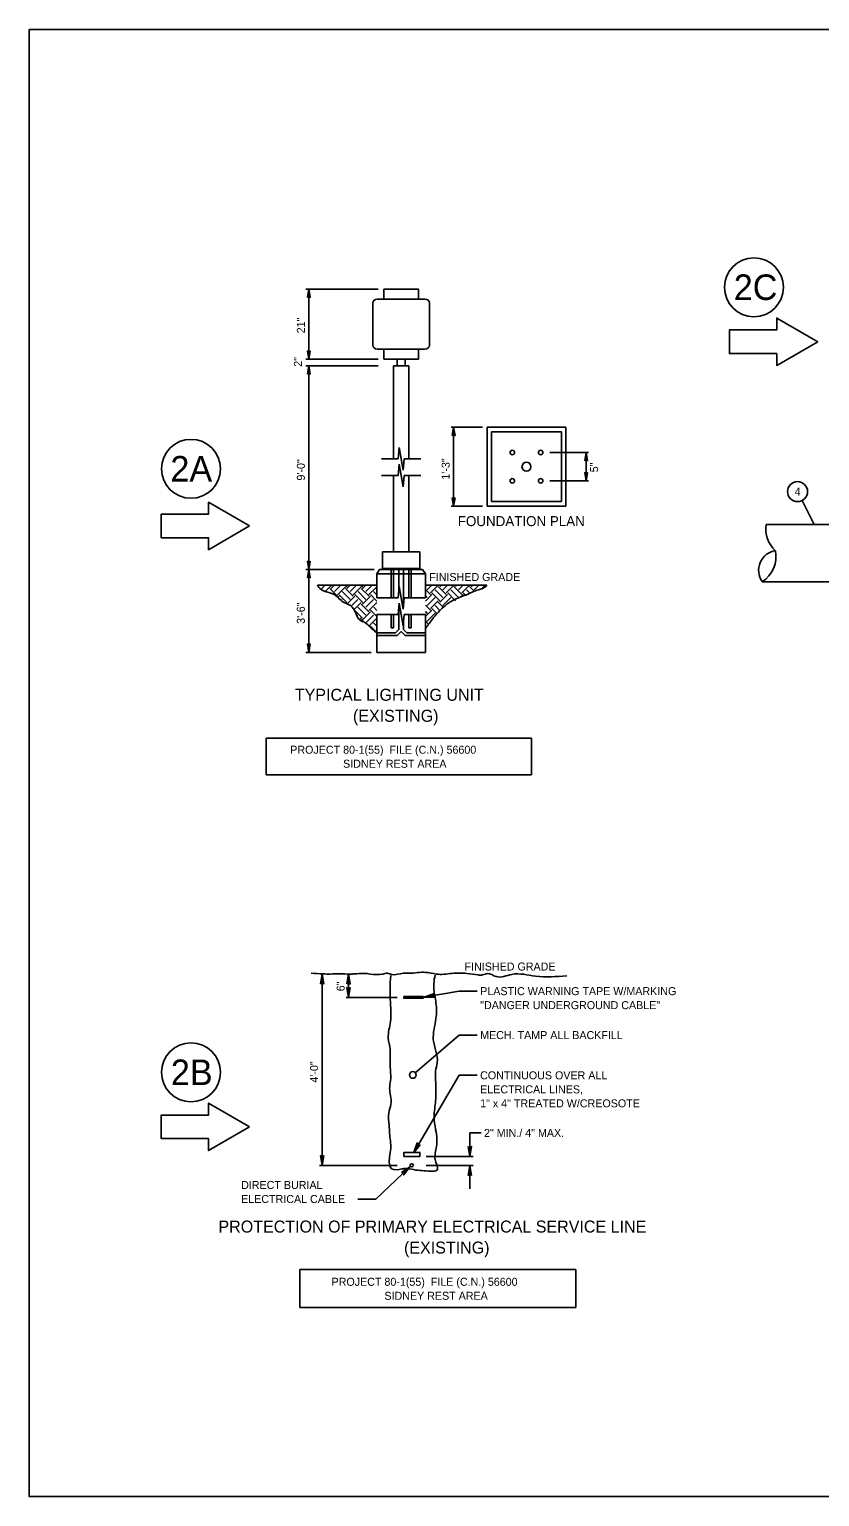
# Model space of a CAD drawing. Extents: x 99968 to 128667, y 90163 to 102182.
# Drawn here: x 105067 to 106253, y 99882 to 102082 of the extents above; entities that cross this region are included whole.
import ezdxf

# ---------------------------------------------------------------- set-up
doc = ezdxf.new("R2010")
doc.units = 0
for name, color, linetype in [('Border Prelim Stamp', 7, 'Continuous'), ('Default', 7, 'Continuous'), ('RD Standard Plans Active', 7, 'Continuous')]:
    doc.layers.add(name, color=color, linetype=linetype)

msp = doc.modelspace()

# ---------------------------------------------------------------- linework, layer by layer
at = {"layer": 'Border Prelim Stamp'}
for points in [[(106250.5, 101613.2), (106189.1, 101648.7), (106189.1, 101631), (106118.1, 101631), (106118.1, 101595.5), (106189.1, 101595.5), (106189.1, 101577.8)], [(105397.8, 101337), (105336.4, 101372.5), (105336.4, 101354.8), (105265.4, 101354.8), (105265.4, 101319.3), (105336.4, 101319.3), (105336.4, 101301.5)], [(105397.8, 100436.3), (105336.4, 100471.8), (105336.4, 100454), (105265.4, 100454), (105265.4, 100418.6), (105336.4, 100418.6), (105336.4, 100400.8)]]:
    msp.add_lwpolyline(points, close=True, dxfattribs=at)
for centre in [(106154.7, 101694.9), (105310, 101422.7), (105310, 100518)]:
    msp.add_circle(centre, 44.2, dxfattribs=at)
at = {"layer": 'Default'}
msp.add_lwpolyline([(105067.5, 102081.5), (108267.2, 102081.5), (108267.2, 99881.9), (105067.5, 99881.9)], close=True, dxfattribs=at)
at = {"layer": 'RD Standard Plans Active'}
for p, q in [((105590.8, 101692.1), (105482.5, 101692.1)), ((105486.9, 101587.1), (105486.9, 101692.1)), ((105599.2, 101692.1), (105651.7, 101692.1)), ((105599.2, 101677.1), (105599.2, 101692.1)), ((105651.7, 101677.1), (105651.7, 101692.1)), ((105582.9, 101671.1), (105582.9, 101608.1)), ((105661.2, 101677.1), (105589.6, 101677.1)), ((105667.9, 101671.1), (105667.9, 101608.1)), ((105661.2, 101602.1), (105589.6, 101602.1)), ((105599.2, 101602.1), (105599.2, 101587.1)), ((105651.7, 101602.1), (105651.7, 101587.1)), ((105590.8, 101587.1), (105482.5, 101587.1)), ((105599.2, 101587.1), (105651.7, 101587.1)), ((105619.6, 101587.1), (105619.6, 101577.1)), ((105631.2, 101587.1), (105631.2, 101577.1)), ((105590.8, 101577.1), (105482.5, 101577.1)), ((105486.9, 101271.8), (105486.9, 101577.1)), ((105614, 101577.1), (105614, 101437.8)), ((105614, 101577.1), (105636.9, 101577.1)), ((105636.9, 101577.1), (105636.9, 101437.8)), ((105747.7, 101484.9), (105700.4, 101484.9)), ((105704.2, 101366.8), (105704.2, 101484.9)), ((105754.4, 101484.9), (105872.6, 101484.9)), ((105754.4, 101484.9), (105754.4, 101366.8)), ((105761.2, 101478.2), (105865.8, 101478.2)), ((105761.2, 101478.2), (105761.2, 101373.5)), ((105865.8, 101478.2), (105865.8, 101373.5)), ((105872.6, 101484.9), (105872.6, 101366.8)), ((105621, 101437.8), (105622.4, 101454.7)), ((105622.4, 101454.7), (105628.4, 101420.9)), ((105906.6, 101447.1), (105848.3, 101447.1)), ((105903, 101404.6), (105903, 101447.1)), ((105596, 101437.8), (105621, 101437.8)), ((105621, 101412.8), (105622.4, 101429.7)), ((105622.4, 101429.7), (105628.4, 101395.9)), ((105629.8, 101437.8), (105628.4, 101420.9)), ((105629.8, 101437.8), (105654.8, 101437.8)), ((105596, 101412.8), (105621, 101412.8)), ((105614, 101412.8), (105614, 101298.5)), ((105629.8, 101412.8), (105628.4, 101395.9)), ((105629.8, 101412.8), (105654.8, 101412.8)), ((105636.9, 101412.8), (105636.9, 101298.5)), ((105906.6, 101404.6), (105848.3, 101404.6)), ((105747.7, 101366.8), (105700.4, 101366.8)), ((105754.4, 101366.8), (105872.6, 101366.8)), ((105761.2, 101373.5), (105865.8, 101373.5)), ((106226.9, 101375), (106244.9, 101339)), ((106173, 101339), (106396.4, 101339)), ((105597.3, 101298.5), (105653.5, 101298.5)), ((105597.3, 101273.5), (105597.3, 101298.5)), ((105653.5, 101273.5), (105653.5, 101298.5)), ((105584.8, 101271.8), (105482.5, 101271.8)), ((105486.9, 101147.6), (105486.9, 101271.8)), ((105593.1, 101271.8), (105589, 101265.1)), ((105593.1, 101271.8), (105657.7, 101271.8)), ((105597.3, 101273.5), (105653.5, 101273.5)), ((105597.3, 101271.8), (105597.3, 101273.5)), ((105610.6, 101271.8), (105610.6, 101229.4)), ((105613.9, 101271.8), (105613.9, 101229.4)), ((105622.1, 101242.1), (105622.1, 101271.8)), ((105628.7, 101216.8), (105628.7, 101271.8)), ((105636.9, 101229.4), (105636.9, 101271.8)), ((105640.2, 101229.4), (105640.2, 101271.8)), ((105653.5, 101271.8), (105653.5, 101273.5)), ((105657.7, 101271.8), (105661.9, 101265.1)), ((105589, 101248.5), (105499.8, 101248.5)), ((105500.8, 101247.2), (105502.1, 101248.5)), ((105505, 101241.9), (105511.6, 101248.5)), ((105517.8, 101248.5), (105520.6, 101245.7)), ((105520.5, 101243.4), (105525.5, 101248.5)), ((105525.2, 101238.7), (105535, 101248.5)), ((105541.6, 101248.5), (105544.2, 101245.8)), ((105544.1, 101243.4), (105549.1, 101248.5)), ((105548.8, 101238.7), (105558.5, 101248.5)), ((105565, 101248.5), (105567.7, 101245.8)), ((105567.6, 101243.5), (105572.5, 101248.5)), ((105572.3, 101238.8), (105581.9, 101248.5)), ((105588.7, 101248.5), (105589, 101248.2)), ((105589, 101265.1), (105661.9, 101265.1)), ((105589, 101265.1), (105589, 101229.4)), ((105661.9, 101265.1), (105661.9, 101229.4)), ((105661.9, 101248.1), (105662.2, 101248.5)), ((105661.9, 101248.5), (105753.9, 101248.5)), ((105664.6, 101241.3), (105671.7, 101248.5)), ((105669.3, 101236.6), (105681.1, 101248.4)), ((105683.4, 101246.1), (105685.8, 101248.5)), ((105683.5, 101248.5), (105683.6, 101248.4)), ((105688.1, 101241.3), (105695.2, 101248.5)), ((105692.8, 101236.6), (105704.6, 101248.4)), ((105706.9, 101246.1), (105709.2, 101248.5)), ((105706.9, 101248.5), (105707, 101248.4)), ((105711.6, 101241.4), (105718.6, 101248.5)), ((105716.3, 101236.7), (105728.1, 101248.5)), ((105730.5, 101246.1), (105732.8, 101248.5)), ((105735.2, 101241.4), (105742.2, 101248.5)), ((105746.3, 101243.1), (105751.6, 101248.5)), ((106166.9, 101253.5), (106396.4, 101253.5)), ((105511.4, 101238.9), (105518.2, 101245.7)), ((105513.6, 101238.7), (105514.4, 101237.9)), ((105518.3, 101243.4), (105530.1, 101231.7)), ((105529.9, 101234), (105541.7, 101245.8)), ((105530.8, 101230.1), (105532.3, 101231.7)), ((105532.3, 101234), (105544.1, 101222.2)), ((105535.4, 101225.3), (105537, 101226.9)), ((105537, 101238.7), (105548.8, 101226.9)), ((105541.7, 101243.4), (105553.5, 101231.7)), ((105544.7, 101220.7), (105555.8, 101231.7)), ((105550.2, 101216.8), (105560.5, 101227)), ((105553.5, 101234), (105565.3, 101245.8)), ((105556, 101234.1), (105567.7, 101222.3)), ((105560.7, 101238.8), (105572.5, 101227)), ((105565.4, 101243.5), (105577.2, 101231.7)), ((105567.6, 101220), (105579.4, 101231.7)), ((105572.3, 101215.2), (105584.1, 101227)), ((105577, 101234.1), (105588.8, 101245.9)), ((105579.4, 101234.1), (105589, 101224.5)), ((105584.1, 101238.8), (105589, 101233.9)), ((105588.8, 101243.5), (105589, 101243.3)), ((105589, 101229.4), (105621, 101229.4)), ((105621, 101229.4), (105622.4, 101246.4)), ((105622.4, 101246.4), (105628.4, 101212.5)), ((105629.8, 101229.4), (105628.4, 101212.5)), ((105629.8, 101229.4), (105661.9, 101229.4)), ((105661.9, 101241.8), (105669.4, 101234.3)), ((105661.9, 101224.5), (105671.6, 101234.3)), ((105661.9, 101232.4), (105664.7, 101229.6)), ((105664.6, 101217.8), (105676.3, 101229.6)), ((105671.6, 101236.6), (105683.4, 101224.8)), ((105676.3, 101241.3), (105688.1, 101229.6)), ((105681.1, 101246.1), (105692.8, 101234.3)), ((105683.3, 101222.6), (105695.1, 101234.4)), ((105688, 101217.9), (105699.8, 101229.6)), ((105695.3, 101236.7), (105707.1, 101224.9)), ((105700, 101241.4), (105711.9, 101229.5)), ((105704.7, 101246.1), (105716.5, 101234.4)), ((105715, 101230.7), (105718.7, 101234.4)), ((105718.7, 101236.7), (105722, 101233.4)), ((105723.4, 101241.4), (105728.6, 101236.2)), ((105728.1, 101246.1), (105735.3, 101239)), ((105541.4, 101221.9), (105541.7, 101222.2)), ((105554.2, 101211.3), (105565.2, 101222.3)), ((105555.8, 101210.5), (105567.6, 101198.7)), ((105560.5, 101215.2), (105572.3, 101203.5)), ((105565.2, 101220), (105577, 101208.2)), ((105567.5, 101196.5), (105579.3, 101208.2)), ((105577, 101210.5), (105588.8, 101222.3)), ((105579.4, 101210.6), (105589, 101201.1)), ((105584.2, 101215.3), (105589, 101210.5)), ((105588.9, 101220), (105589, 101220)), ((105589, 101204.4), (105621, 101204.4)), ((105589, 101204.4), (105589, 101147.6)), ((105610.6, 101204.4), (105610.6, 101184.3)), ((105613.9, 101204.4), (105613.9, 101184.3)), ((105621, 101204.4), (105622.4, 101221.4)), ((105622.1, 101181.9), (105622.1, 101217.1)), ((105622.4, 101221.4), (105628.4, 101187.5)), ((105629.8, 101204.4), (105628.4, 101187.5)), ((105629.8, 101204.4), (105661.9, 101204.4)), ((105636.9, 101184.3), (105636.9, 101204.4)), ((105640.2, 101184.3), (105640.2, 101204.4)), ((105661.9, 101218.1), (105669.3, 101210.7)), ((105661.9, 101201.1), (105671.5, 101210.8)), ((105661.9, 101208.7), (105664.6, 101206)), ((105661.9, 101204.4), (105661.9, 101147.6)), ((105664.5, 101194.3), (105676.3, 101206.1)), ((105669.3, 101213.1), (105681.1, 101224.8)), ((105671.7, 101213.1), (105679.2, 101205.6)), ((105676.4, 101217.9), (105683.7, 101210.5)), ((105681.1, 101222.6), (105688.5, 101215.2)), ((105559.6, 101202.5), (105560.5, 101203.5)), ((105563.1, 101196.6), (105565.2, 101198.7)), ((105565.3, 101196.5), (105568.2, 101193.6)), ((105572.2, 101191.8), (105584, 101203.5)), ((105576.9, 101187), (105588.7, 101198.8)), ((105579.3, 101187), (105589, 101177.4)), ((105584, 101191.8), (105589, 101186.8)), ((105588.7, 101196.5), (105589, 101196.2)), ((105610.6, 101184.3), (105613.9, 101184.3)), ((105622.1, 101181.9), (105616.9, 101176.7)), ((105628.7, 101181.9), (105628.7, 101191.8)), ((105628.7, 101181.9), (105633.9, 101176.7)), ((105636.9, 101184.3), (105640.2, 101184.3)), ((105661.9, 101194.7), (105666.7, 101189.8)), ((105661.9, 101185.3), (105662.7, 101184.4)), ((105588.8, 101173), (105589, 101172.8)), ((105616.9, 101176.7), (105589, 101176.7)), ((105619.4, 101172.6), (105589, 101172.6)), ((105625.4, 101178.6), (105619.4, 101172.6)), ((105625.4, 101178.6), (105631.4, 101172.6)), ((105631.4, 101172.6), (105661.9, 101172.6)), ((105633.9, 101176.7), (105661.9, 101176.7)), ((105580.6, 101147.6), (105482.5, 101147.6)), ((105588.6, 101149.4), (105589, 101149.1)), ((105661.9, 101147.6), (105589, 101147.6)), ((105506.8, 100378.4), (105506.8, 100665.4)), ((105546.6, 100630.4), (105546.6, 100665.5)), ((105712.4, 100639.7), (105659.6, 100630.9)), ((105739.6, 100639.7), (105712.4, 100639.7)), ((105619.5, 100630.4), (105543.1, 100630.4)), ((105712.4, 100573.8), (105646.7, 100517.3)), ((105739.5, 100573.8), (105712.4, 100573.8)), ((105712.3, 100513.5), (105644.3, 100398)), ((105739.5, 100513.5), (105712.3, 100513.5)), ((105728.6, 100392), (105728.6, 100427.1)), ((105745.3, 100427.1), (105728.6, 100427.1)), ((105663, 100392), (105733.4, 100392)), ((105619.5, 100378.4), (105503.1, 100378.4)), ((105587.6, 100328.1), (105638.2, 100376.4)), ((105663, 100378.4), (105733.4, 100378.4)), ((105728.6, 100343.3), (105728.6, 100378.4)), ((105587.6, 100328.1), (105560.5, 100328.1))]:
    msp.add_line(p, q, dxfattribs=at)
for points in [[(105484.8, 101679.7), (105486.9, 101692.1), (105489, 101679.7), (105486.9, 101681.6)], [(105489, 101599.5), (105486.9, 101587.1), (105484.8, 101599.5), (105486.9, 101597.6)], [(105484.8, 101564.7), (105486.9, 101577.1), (105489, 101564.7), (105486.9, 101566.6)], [(105702.1, 101472.5), (105704.2, 101484.9), (105706.3, 101472.5), (105704.2, 101474.4)], [(105900.9, 101434.7), (105903, 101447.1), (105905.1, 101434.7), (105903, 101436.7)], [(105905.1, 101417), (105903, 101404.6), (105900.9, 101417), (105903, 101415)], [(105706.3, 101379.2), (105704.2, 101366.8), (105702.1, 101379.2), (105704.2, 101377.3)], [(105489, 101284.2), (105486.9, 101271.8), (105484.8, 101284.2), (105486.9, 101282.3)], [(105484.8, 101259.4), (105486.9, 101271.8), (105489, 101259.4), (105486.9, 101261.3)], [(105489, 101160.1), (105486.9, 101147.6), (105484.8, 101160.1), (105486.9, 101158.1)], [(105423.1, 101018.7), (105820.8, 101018.7), (105820.8, 100964.2), (105423.1, 100964.2)], [(105504.2, 100650.5), (105506.8, 100665.4), (105509.3, 100650.5), (105506.8, 100652.9)], [(105544.1, 100650.5), (105546.6, 100665.5), (105549.1, 100650.5), (105546.6, 100652.9)], [(105549.1, 100645.3), (105546.6, 100630.4), (105544.1, 100645.3), (105546.6, 100642.9)], [(105674.8, 100630.9), (105659.6, 100630.9), (105673.9, 100635.9), (105672, 100633)], [(105629.5, 100631.7), (105658.3, 100631.7), (105658.3, 100629.1), (105629.5, 100629.1)], [(105654, 100409.5), (105644.3, 100398), (105649.6, 100412.1), (105650.6, 100408.8)], [(105509.3, 100393.3), (105506.8, 100378.4), (105504.2, 100393.3), (105506.8, 100390.9)], [(105629.5, 100392), (105653.5, 100392), (105653.5, 100398), (105629.5, 100398)], [(105726.1, 100406.9), (105728.6, 100392), (105731.2, 100406.9), (105728.6, 100404.5)], [(105625.7, 100367.9), (105638.2, 100376.4), (105629.2, 100364.3), (105629.1, 100367.7)], [(105731.2, 100363.5), (105728.6, 100378.4), (105726.1, 100363.5), (105728.6, 100365.8)], [(105473.5, 100222.2), (105887.3, 100222.2), (105887.3, 100165.5), (105473.5, 100165.5)]]:
    msp.add_lwpolyline(points, close=True, dxfattribs=at)
for centre, radius in [((105792.2, 101447.1), 3.37), ((105834.8, 101447.1), 3.37), ((105813.5, 101425.8), 6.75), ((105792.2, 101404.6), 3.37), ((105834.8, 101404.6), 3.37), ((106220.2, 101388.5), 15), ((105642.9, 100514), 5), ((105641.2, 100378.6), 2.4)]:
    msp.add_circle(centre, radius, dxfattribs=at)
for centre, radius, start, end in [((106216.4, 101332.5), 43.9, 171.491, 227.9134), ((106191.7, 101270.4), 29.9, 99.029, 214.26), ((106144, 101290.9), 43.9, 301.4423, 11.8467)]:
    msp.add_arc(centre, radius, start, end, dxfattribs=at)
for centre, major_axis, start_param, end_param in [((105589.6, 101671.1), (-6.67, 0), 4.712389, 6.283185), ((105661.2, 101671.1), (-6.67, 0), 3.141593, 4.712389), ((105589.6, 101608.1), (6.67, 0), 3.141593, 4.712389), ((105661.2, 101608.1), (6.67, 0), 4.712389, 6.283185)]:
    msp.add_ellipse(centre, major_axis=major_axis, ratio=0.9, start_param=start_param, end_param=end_param, dxfattribs=at)
for points in [[(105499.8, 101248.5), (105504.8, 101242.1), (105513.4, 101238.3), (105526, 101233.7), (105537.1, 101223.9), (105549.4, 101217.7), (105557.2, 101206.6), (105563.9, 101195.5), (105570.3, 101192.6), (105584.5, 101180.1), (105589, 101176.9)], [(105661.5, 101182.8), (105671.6, 101196.4), (105684.7, 101211.5), (105705.6, 101226.9), (105724.6, 101234.5), (105741.3, 101241.5), (105752.4, 101246.4), (105754.1, 101248.3)], [(105490.6, 100666.6), (105508.4, 100665.6), (105518.7, 100665.3), (105533.5, 100665.9), (105548.2, 100665.3), (105555.2, 100665.6), (105569.6, 100666.3), (105579, 100665.3), (105597.7, 100665.3), (105604.4, 100666.6), (105611.5, 100664.7), (105628.5, 100666.6), (105637.9, 100666.6), (105662, 100667.9), (105678.1, 100665.3), (105689.4, 100665), (105701.5, 100666.3), (105724.2, 100666.3), (105741, 100664), (105747.7, 100664), (105754.7, 100666.1), (105768.1, 100661.5), (105791.5, 100664.8), (105827, 100662.2), (105873.8, 100662.8)], [(105609.8, 100663), (105608.8, 100643.5), (105609.4, 100621.5), (105609.4, 100594.2), (105606.1, 100569.5), (105608.8, 100552.7), (105608.8, 100540.3), (105609.4, 100521.5), (105609.4, 100505.3), (105608.1, 100494.2), (105609.4, 100483.2), (105610.1, 100470.2), (105606.8, 100457.2), (105607.4, 100438.4), (105608.1, 100426.7), (105609.8, 100404), (105608.1, 100391), (105611.1, 100373.5), (105626.5, 100373.1), (105633.5, 100373.8), (105647.6, 100371.5), (105660, 100370.5), (105680.1, 100372.8), (105677.4, 100383.5), (105676.4, 100387.1), (105678.4, 100406.9), (105679.1, 100418.3), (105677.1, 100432.5), (105675, 100451.4), (105677.1, 100475.4), (105677.7, 100489.7), (105677.1, 100506.6), (105677.1, 100519.5), (105679.7, 100532.5), (105673.7, 100566.9), (105677.7, 100598.8), (105677.7, 100621.5), (105675.7, 100633.8), (105674.4, 100651.3), (105676.4, 100663.7)]]:
    msp.add_spline(points, degree=3, dxfattribs=at)

# ---------------------------------------------------------------- texts
at = {"layer": 'Border Prelim Stamp'}
for s, p in [('2C', (106124.5, 101675.8)), ('2A', (105279.2, 101403.6)), ('2B', (105279.9, 100498.9))]:
    msp.add_text(s, height=38.31, dxfattribs=at).set_placement(p)
at = {"layer": 'RD Standard Plans Active'}
for s, p in [('21"', (105480.9, 101625.8)), ('2"', (105476.5, 101575.7)), ('9\'-0"', (105480.9, 101405.1)), ('1\'-3"', (105698.2, 101406.5)), ('5"', (105921, 101417.5)), ('3\'-6"', (105480.9, 101190.3)), ('6"', (105540.6, 100639.5)), ('4\'-0"', (105500.8, 100502.5))]:
    msp.add_text(s, height=12, rotation=90, dxfattribs=at).set_placement(p)
for s, height, p in [('4', 12, (106215.8, 101382.5)), ('FOUNDATION PLAN', 15, (105710.4, 101336.8)), ('FINISHED GRADE', 12, (105667.6, 101254.5)), ('TYPICAL LIGHTING UNIT', 18, (105465.9, 101075)), ('(EXISTING)', 18, (105553.1, 101043.5)), ('PROJECT 80-1(55)  FILE (C.N.) 56600', 12, (105459, 100995.6)), ('SIDNEY REST AREA', 12, (105538.3, 100974.6)), ('FINISHED GRADE', 12, (105720.6, 100670.6)), (' PLASTIC WARNING TAPE W/MARKING', 12, (105739.6, 100633.7)), (' "DANGER UNDERGROUND CABLE"', 12, (105739.6, 100612.7)), (' MECH. TAMP ALL BACKFILL', 12, (105739.5, 100567.8)), (' CONTINUOUS OVER ALL', 12, (105739.5, 100507.5)), (' ELECTRICAL LINES,', 12, (105739.5, 100486.5)), (' 1" x 4" TREATED W/CREOSOTE', 12, (105739.5, 100465.5)), (' 2" MIN./ 4" MAX.', 12, (105745.3, 100421.1)), ('DIRECT BURIAL', 12, (105385.3, 100343.1)), ('ELECTRICAL CABLE ', 12, (105385.3, 100322.1)), ('PROTECTION OF PRIMARY ELECTRICAL SERVICE LINE', 18, (105351.3, 100277.8)), ('(EXISTING)', 18, (105629.7, 100246.3)), ('PROJECT 80-1(55)  FILE (C.N.) 56600', 12, (105521, 100198)), ('SIDNEY REST AREA', 12, (105600.3, 100177))]:
    msp.add_text(s, height=height, dxfattribs=at).set_placement(p)

doc.saveas('drawing.dxf')
